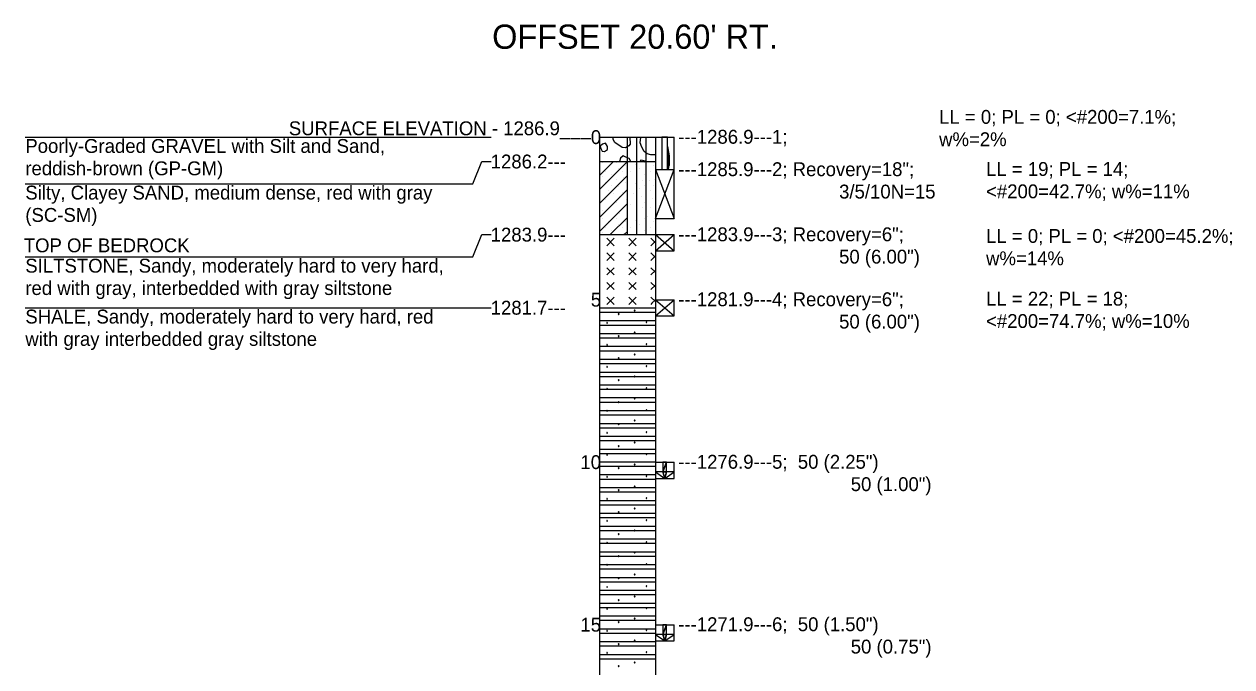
# Model space of a CAD drawing. Extents: x -6 to 173, y 24 to 64.
# Drawn here: x 138.21 to 149.01, y 44.86 to 50.61 of the extents above; entities that cross this region are included whole.
import ezdxf

# ---------------------------------------------------------------- set-up
doc = ezdxf.new("R2010")
doc.units = 0

# ---------------------------------------------------------------- blocks, each defined once
blk = doc.blocks.new('POINT_DISPLAY')
blk.add_line((0, 0), (0, 0))

msp = doc.modelspace()

# ---------------------------------------------------------------- linework, layer by layer
for points in [[(138.218, 49.598), (142.384, 49.598)], [(143.352, 49.598), (144.019, 49.598)], [(143.352, 49.598), (143.352, 39.423)], [(143.624, 49.598), (143.625, 49.534), (143.614, 49.519), (143.584, 49.503), (143.555, 49.504), (143.534, 49.519), (143.51, 49.534), (143.489, 49.549), (143.475, 49.578), (143.475, 49.598)], [(143.602, 49.38), (143.602, 49.598)], [(143.685, 49.38), (143.685, 49.598)], [(143.852, 49.441), (143.812, 49.439), (143.777, 49.449), (143.752, 49.469), (143.729, 49.508), (143.715, 49.548), (143.72, 49.598)], [(143.769, 49.38), (143.769, 49.598)], [(143.852, 49.598), (143.852, 39.423)], [(144.019, 49.307), (144.019, 49.598)], [(143.379, 49.536), (143.359, 49.518), (143.365, 49.496), (143.375, 49.471), (143.397, 49.468), (143.422, 49.488), (143.422, 49.514), (143.405, 49.544), (143.379, 49.536)], [(138.218, 49.181), (142.218, 49.181), (142.301, 49.38), (142.384, 49.38)], [(143.352, 49.38), (143.852, 49.38)], [(143.352, 49.255), (143.477, 49.38)], [(143.352, 49.13), (143.602, 49.38)], [(143.618, 49.408), (143.588, 49.42), (143.563, 49.432), (143.54, 49.41), (143.532, 49.38), (143.631, 49.38), (143.618, 49.408)], [(143.602, 48.726), (143.602, 49.38)], [(143.685, 48.726), (143.685, 49.38)], [(143.764, 49.383), (143.721, 49.391), (143.713, 49.38), (143.764, 49.38), (143.764, 49.383)], [(143.769, 48.726), (143.769, 49.38)], [(143.352, 49.005), (143.602, 49.255)], [(143.852, 49.307), (144.019, 49.307)], [(143.852, 49.307), (144.019, 48.871)], [(143.852, 48.871), (144.019, 49.307)], [(143.852, 49.307), (144.019, 49.307)], [(144.019, 48.871), (144.019, 49.307)], [(143.352, 48.88), (143.602, 49.13)], [(143.352, 48.755), (143.602, 49.005)], [(143.448, 48.726), (143.602, 48.88)], [(143.852, 48.871), (144.019, 48.871)], [(138.218, 48.527), (142.218, 48.527), (142.301, 48.726), (142.384, 48.726)], [(143.352, 48.726), (143.852, 48.726)], [(143.573, 48.726), (143.602, 48.755)], [(143.852, 48.726), (144.019, 48.58)], [(143.852, 48.58), (144.019, 48.726)], [(143.852, 48.726), (144.019, 48.726)], [(144.019, 48.58), (144.019, 48.726)], [(143.483, 48.693), (143.417, 48.627)], [(143.417, 48.693), (143.483, 48.627)], [(143.68, 48.693), (143.614, 48.627)], [(143.614, 48.693), (143.68, 48.627)], [(143.811, 48.693), (143.852, 48.652)], [(143.852, 48.668), (143.811, 48.627)], [(143.483, 48.562), (143.417, 48.496)], [(143.417, 48.562), (143.483, 48.496)], [(143.68, 48.562), (143.614, 48.496)], [(143.614, 48.562), (143.68, 48.496)], [(143.811, 48.562), (143.852, 48.521)], [(143.852, 48.537), (143.811, 48.496)], [(143.852, 48.58), (144.019, 48.58)], [(143.483, 48.43), (143.417, 48.365)], [(143.417, 48.43), (143.483, 48.365)], [(143.68, 48.43), (143.614, 48.365)], [(143.614, 48.43), (143.68, 48.365)], [(143.811, 48.43), (143.852, 48.39)], [(143.852, 48.405), (143.811, 48.365)], [(143.483, 48.299), (143.417, 48.234)], [(143.417, 48.299), (143.483, 48.234)], [(143.68, 48.299), (143.614, 48.234)], [(143.614, 48.299), (143.68, 48.234)], [(143.811, 48.299), (143.852, 48.258)], [(143.852, 48.274), (143.811, 48.234)], [(143.483, 48.168), (143.417, 48.102)], [(143.417, 48.168), (143.483, 48.102)], [(143.68, 48.168), (143.614, 48.102)], [(143.614, 48.168), (143.68, 48.102)], [(143.811, 48.168), (143.852, 48.127)], [(138.218, 48.072), (142.384, 48.072)], [(143.352, 48.072), (143.852, 48.072)], [(143.352, 48.072), (143.852, 48.072)], [(143.852, 48.143), (143.821, 48.112), (143.811, 48.102)], [(143.852, 48.144), (144.019, 47.999)], [(143.852, 47.999), (144.019, 48.144)], [(143.852, 48.144), (144.019, 48.144)], [(144.019, 47.999), (144.019, 48.144)], [(143.352, 48.032), (143.852, 48.032)], [(143.352, 47.957), (143.852, 47.957)], [(143.527, 48.016), (143.525, 48.019), (143.522, 48.019), (143.52, 48.016), (143.522, 48.013), (143.525, 48.013), (143.527, 48.016)], [(143.67, 48.048), (143.668, 48.05), (143.665, 48.05), (143.663, 48.048), (143.665, 48.045), (143.668, 48.045), (143.67, 48.048)], [(143.775, 47.943), (143.773, 47.946), (143.77, 47.946), (143.768, 47.943), (143.77, 47.94), (143.773, 47.94), (143.775, 47.943)], [(143.852, 47.999), (144.019, 47.999)], [(143.352, 47.917), (143.852, 47.917)], [(143.352, 47.842), (143.852, 47.842)], [(143.422, 47.937), (143.421, 47.94), (143.417, 47.94), (143.416, 47.937), (143.417, 47.934), (143.421, 47.934), (143.422, 47.937)], [(143.67, 47.851), (143.668, 47.854), (143.665, 47.854), (143.663, 47.851), (143.665, 47.848), (143.668, 47.848), (143.67, 47.851)], [(143.352, 47.803), (143.852, 47.803)], [(143.352, 47.727), (143.852, 47.727)], [(143.422, 47.74), (143.421, 47.743), (143.417, 47.743), (143.416, 47.74), (143.417, 47.737), (143.421, 47.737), (143.422, 47.74)], [(143.527, 47.819), (143.525, 47.822), (143.522, 47.822), (143.52, 47.819), (143.522, 47.816), (143.525, 47.816), (143.527, 47.819)], [(143.775, 47.746), (143.773, 47.749), (143.77, 47.749), (143.768, 47.746), (143.77, 47.744), (143.773, 47.744), (143.775, 47.746)], [(143.352, 47.688), (143.852, 47.688)], [(143.527, 47.622), (143.525, 47.625), (143.522, 47.625), (143.52, 47.622), (143.522, 47.619), (143.525, 47.619), (143.527, 47.622)], [(143.67, 47.654), (143.668, 47.657), (143.665, 47.657), (143.663, 47.654), (143.665, 47.651), (143.668, 47.651), (143.67, 47.654)], [(143.352, 47.612), (143.852, 47.612)], [(143.352, 47.573), (143.852, 47.573)], [(143.422, 47.543), (143.421, 47.546), (143.417, 47.546), (143.416, 47.543), (143.417, 47.54), (143.421, 47.54), (143.422, 47.543)], [(143.775, 47.55), (143.773, 47.552), (143.77, 47.552), (143.768, 47.55), (143.77, 47.547), (143.773, 47.547), (143.775, 47.55)], [(143.352, 47.497), (143.852, 47.497)], [(143.352, 47.458), (143.852, 47.458)], [(143.527, 47.425), (143.525, 47.428), (143.522, 47.428), (143.52, 47.425), (143.522, 47.422), (143.525, 47.422), (143.527, 47.425)], [(143.67, 47.457), (143.668, 47.46), (143.665, 47.46), (143.663, 47.457), (143.665, 47.454), (143.668, 47.454), (143.67, 47.457)], [(143.352, 47.383), (143.852, 47.383)], [(143.352, 47.343), (143.852, 47.343)], [(143.422, 47.346), (143.421, 47.349), (143.417, 47.349), (143.416, 47.346), (143.417, 47.343), (143.421, 47.343), (143.422, 47.346)], [(143.775, 47.353), (143.773, 47.356), (143.77, 47.356), (143.768, 47.353), (143.77, 47.35), (143.773, 47.35), (143.775, 47.353)], [(143.352, 47.268), (143.852, 47.268)], [(143.352, 47.228), (143.852, 47.228)], [(143.527, 47.228), (143.525, 47.231), (143.522, 47.231), (143.52, 47.228), (143.522, 47.225), (143.525, 47.225), (143.527, 47.228)], [(143.67, 47.26), (143.668, 47.263), (143.665, 47.263), (143.663, 47.26), (143.665, 47.257), (143.668, 47.257), (143.67, 47.26)], [(143.352, 47.153), (143.852, 47.153)], [(143.352, 47.114), (143.852, 47.114)], [(143.422, 47.149), (143.421, 47.152), (143.417, 47.152), (143.416, 47.149), (143.417, 47.146), (143.421, 47.146), (143.422, 47.149)], [(143.775, 47.156), (143.773, 47.159), (143.77, 47.159), (143.768, 47.156), (143.77, 47.153), (143.773, 47.153), (143.775, 47.156)], [(143.352, 47.038), (143.852, 47.038)], [(143.352, 46.999), (143.852, 46.999)], [(143.527, 47.031), (143.525, 47.034), (143.522, 47.034), (143.52, 47.032), (143.522, 47.029), (143.525, 47.029), (143.527, 47.031)], [(143.67, 47.063), (143.668, 47.066), (143.665, 47.066), (143.663, 47.063), (143.665, 47.061), (143.668, 47.061), (143.67, 47.063)], [(143.352, 46.923), (143.852, 46.923)], [(143.352, 46.884), (143.852, 46.884)], [(143.422, 46.953), (143.421, 46.955), (143.417, 46.955), (143.416, 46.953), (143.417, 46.95), (143.421, 46.95), (143.422, 46.953)], [(143.67, 46.867), (143.668, 46.869), (143.665, 46.869), (143.663, 46.867), (143.665, 46.864), (143.668, 46.864), (143.67, 46.867)], [(143.775, 46.959), (143.773, 46.962), (143.77, 46.962), (143.768, 46.959), (143.77, 46.956), (143.773, 46.956), (143.775, 46.959)], [(143.352, 46.808), (143.852, 46.808)], [(143.352, 46.769), (143.852, 46.769)], [(143.422, 46.756), (143.421, 46.759), (143.417, 46.759), (143.416, 46.756), (143.417, 46.753), (143.421, 46.753), (143.422, 46.756)], [(143.527, 46.835), (143.525, 46.838), (143.522, 46.838), (143.52, 46.835), (143.522, 46.832), (143.525, 46.832), (143.527, 46.835)], [(143.775, 46.762), (143.773, 46.765), (143.77, 46.765), (143.768, 46.762), (143.77, 46.759), (143.773, 46.759), (143.775, 46.762)], [(143.352, 46.694), (143.852, 46.694)], [(143.352, 46.654), (143.852, 46.654)], [(143.67, 46.67), (143.668, 46.672), (143.665, 46.672), (143.663, 46.67), (143.665, 46.667), (143.668, 46.667), (143.67, 46.67)], [(143.852, 46.691), (144.019, 46.691)], [(144.019, 46.545), (144.019, 46.691)], [(143.352, 46.579), (143.852, 46.579)], [(143.352, 46.539), (143.852, 46.539)], [(143.422, 46.559), (143.421, 46.562), (143.417, 46.562), (143.416, 46.559), (143.417, 46.556), (143.421, 46.556), (143.422, 46.559)], [(143.527, 46.638), (143.525, 46.641), (143.522, 46.641), (143.52, 46.638), (143.522, 46.635), (143.525, 46.635), (143.527, 46.638)], [(143.775, 46.565), (143.773, 46.568), (143.77, 46.568), (143.768, 46.565), (143.77, 46.563), (143.773, 46.563), (143.775, 46.565)], [(143.852, 46.545), (144.019, 46.545)], [(143.352, 46.464), (143.852, 46.464)], [(143.527, 46.441), (143.525, 46.444), (143.522, 46.444), (143.52, 46.441), (143.522, 46.438), (143.525, 46.438), (143.527, 46.441)], [(143.67, 46.473), (143.668, 46.476), (143.665, 46.476), (143.663, 46.473), (143.665, 46.47), (143.668, 46.47), (143.67, 46.473)], [(143.352, 46.425), (143.852, 46.425)], [(143.352, 46.349), (143.852, 46.349)], [(143.422, 46.362), (143.421, 46.365), (143.417, 46.365), (143.416, 46.362), (143.417, 46.359), (143.421, 46.359), (143.422, 46.362)], [(143.775, 46.368), (143.773, 46.371), (143.77, 46.371), (143.768, 46.368), (143.77, 46.366), (143.773, 46.366), (143.775, 46.368)], [(143.352, 46.31), (143.852, 46.31)], [(143.352, 46.234), (143.852, 46.234)], [(143.527, 46.244), (143.525, 46.247), (143.522, 46.247), (143.52, 46.244), (143.522, 46.241), (143.525, 46.241), (143.527, 46.244)], [(143.67, 46.276), (143.668, 46.279), (143.665, 46.279), (143.663, 46.276), (143.665, 46.273), (143.668, 46.273), (143.67, 46.276)], [(143.352, 46.195), (143.852, 46.195)], [(143.352, 46.119), (143.852, 46.119)], [(143.422, 46.165), (143.421, 46.168), (143.417, 46.168), (143.416, 46.165), (143.417, 46.162), (143.421, 46.162), (143.422, 46.165)], [(143.775, 46.172), (143.773, 46.175), (143.77, 46.175), (143.768, 46.172), (143.77, 46.169), (143.773, 46.169), (143.775, 46.172)], [(143.352, 46.08), (143.852, 46.08)], [(143.352, 46.005), (143.852, 46.005)], [(143.527, 46.047), (143.525, 46.05), (143.522, 46.05), (143.52, 46.047), (143.522, 46.044), (143.525, 46.044), (143.527, 46.047)], [(143.67, 46.079), (143.668, 46.082), (143.665, 46.082), (143.663, 46.079), (143.665, 46.076), (143.668, 46.076), (143.67, 46.079)], [(143.352, 45.965), (143.852, 45.965)], [(143.422, 45.968), (143.421, 45.971), (143.417, 45.971), (143.416, 45.968), (143.417, 45.965), (143.421, 45.965), (143.422, 45.968)], [(143.775, 45.975), (143.773, 45.978), (143.77, 45.978), (143.768, 45.975), (143.77, 45.972), (143.773, 45.972), (143.775, 45.975)], [(143.352, 45.89), (143.852, 45.89)], [(143.352, 45.85), (143.852, 45.85)], [(143.527, 45.85), (143.525, 45.853), (143.522, 45.853), (143.52, 45.85), (143.522, 45.848), (143.525, 45.848), (143.527, 45.85)], [(143.67, 45.882), (143.668, 45.885), (143.665, 45.885), (143.663, 45.882), (143.665, 45.879), (143.668, 45.879), (143.67, 45.882)], [(143.352, 45.775), (143.852, 45.775)], [(143.352, 45.736), (143.852, 45.736)], [(143.422, 45.771), (143.421, 45.774), (143.417, 45.774), (143.416, 45.771), (143.417, 45.769), (143.421, 45.769), (143.422, 45.771)], [(143.67, 45.685), (143.668, 45.688), (143.665, 45.688), (143.663, 45.685), (143.665, 45.683), (143.668, 45.683), (143.67, 45.685)], [(143.775, 45.778), (143.773, 45.781), (143.77, 45.781), (143.768, 45.778), (143.77, 45.775), (143.773, 45.775), (143.775, 45.778)], [(143.352, 45.66), (143.852, 45.66)], [(143.352, 45.621), (143.852, 45.621)], [(143.422, 45.575), (143.421, 45.577), (143.417, 45.577), (143.416, 45.575), (143.417, 45.572), (143.421, 45.572), (143.422, 45.575)], [(143.527, 45.654), (143.525, 45.656), (143.522, 45.656), (143.52, 45.654), (143.522, 45.651), (143.525, 45.651), (143.527, 45.654)], [(143.775, 45.581), (143.773, 45.584), (143.77, 45.584), (143.768, 45.581), (143.77, 45.578), (143.773, 45.578), (143.775, 45.581)], [(143.352, 45.545), (143.852, 45.545)], [(143.352, 45.506), (143.852, 45.506)], [(143.527, 45.457), (143.525, 45.46), (143.522, 45.46), (143.52, 45.457), (143.522, 45.454), (143.525, 45.454), (143.527, 45.457)], [(143.67, 45.489), (143.668, 45.491), (143.665, 45.491), (143.663, 45.489), (143.665, 45.486), (143.668, 45.486), (143.67, 45.489)], [(143.352, 45.43), (143.852, 45.43)], [(143.352, 45.391), (143.852, 45.391)], [(143.422, 45.378), (143.421, 45.381), (143.417, 45.381), (143.416, 45.378), (143.417, 45.375), (143.421, 45.375), (143.422, 45.378)], [(143.775, 45.384), (143.773, 45.387), (143.77, 45.387), (143.768, 45.384), (143.77, 45.381), (143.773, 45.381), (143.775, 45.384)], [(143.352, 45.316), (143.852, 45.316)], [(143.352, 45.276), (143.852, 45.276)], [(143.527, 45.26), (143.525, 45.263), (143.522, 45.263), (143.52, 45.26), (143.522, 45.257), (143.525, 45.257), (143.527, 45.26)], [(143.67, 45.292), (143.668, 45.295), (143.665, 45.295), (143.663, 45.292), (143.665, 45.289), (143.668, 45.289), (143.67, 45.292)], [(143.352, 45.201), (143.852, 45.201)], [(143.352, 45.161), (143.852, 45.161)], [(143.422, 45.181), (143.421, 45.184), (143.417, 45.184), (143.416, 45.181), (143.417, 45.178), (143.421, 45.178), (143.422, 45.181)], [(143.775, 45.187), (143.773, 45.19), (143.77, 45.19), (143.768, 45.187), (143.77, 45.185), (143.773, 45.185), (143.775, 45.187)], [(143.852, 45.237), (144.019, 45.237)], [(144.019, 45.092), (144.019, 45.237)], [(143.352, 45.086), (143.852, 45.086)], [(143.352, 45.047), (143.852, 45.047)], [(143.527, 45.063), (143.525, 45.066), (143.522, 45.066), (143.52, 45.063), (143.522, 45.06), (143.525, 45.06), (143.527, 45.063)], [(143.67, 45.095), (143.668, 45.098), (143.665, 45.098), (143.663, 45.095), (143.665, 45.092), (143.668, 45.092), (143.67, 45.095)], [(143.852, 45.092), (144.019, 45.092)], [(143.352, 44.971), (143.852, 44.971)], [(143.352, 44.932), (143.852, 44.932)], [(143.422, 44.984), (143.421, 44.987), (143.417, 44.987), (143.416, 44.984), (143.417, 44.981), (143.421, 44.981), (143.422, 44.984)], [(143.775, 44.991), (143.773, 44.993), (143.77, 44.993), (143.768, 44.991), (143.77, 44.988), (143.773, 44.988), (143.775, 44.991)], [(143.527, 44.866), (143.525, 44.869), (143.522, 44.869), (143.52, 44.866), (143.522, 44.863), (143.525, 44.863), (143.527, 44.866)], [(143.67, 44.898), (143.668, 44.901), (143.665, 44.901), (143.663, 44.898), (143.665, 44.895), (143.668, 44.895), (143.67, 44.898)]]:
    msp.add_lwpolyline(points)
for points in [[(143.91, 49.598), (143.91, 49.307), (143.96, 49.307), (143.96, 49.598)], [(143.975, 49.431), (143.969, 49.473), (143.96, 49.513), (143.975, 49.431)], [(143.96, 49.513), (143.96, 49.307), (143.975, 49.431), (143.96, 49.513)], [(143.96, 49.307), (143.975, 49.348), (143.975, 49.431), (143.96, 49.307)], [(143.96, 49.307), (143.969, 49.307), (143.975, 49.348), (143.96, 49.307)], [(143.975, 49.348), (143.977, 49.389), (143.975, 49.431), (143.975, 49.348)], [(143.919, 46.604), (143.952, 46.604), (143.952, 46.691), (143.919, 46.604)], [(143.919, 46.604), (143.952, 46.691), (143.919, 46.691), (143.919, 46.604)], [(143.919, 46.604), (143.852, 46.604), (143.935, 46.545), (143.919, 46.604)], [(143.919, 46.604), (143.935, 46.545), (143.952, 46.604), (143.919, 46.604)], [(143.935, 46.545), (144.019, 46.604), (143.952, 46.604), (143.935, 46.545)], [(143.919, 45.15), (143.852, 45.15), (143.935, 45.092), (143.919, 45.15)], [(143.919, 45.15), (143.952, 45.15), (143.952, 45.237), (143.919, 45.15)], [(143.919, 45.15), (143.952, 45.237), (143.919, 45.237), (143.919, 45.15)], [(143.919, 45.15), (143.935, 45.092), (143.952, 45.15), (143.919, 45.15)], [(143.935, 45.092), (144.019, 45.15), (143.952, 45.15), (143.935, 45.092)]]:
    msp.add_lwpolyline(points, close=True)

# ---------------------------------------------------------------- block references
at = {"xscale": 0.01, "yscale": 0.01}
for p in [(143.381, 49.367), (143.506, 49.367), (143.671, 49.355), (143.756, 49.367), (143.356, 49.317), (143.381, 49.242), (143.406, 49.292), (143.431, 49.342), (143.456, 49.267), (143.523, 49.319), (143.556, 49.292), (143.581, 49.342), (143.631, 49.292), (143.681, 49.242), (143.706, 49.317), (143.756, 49.267), (143.806, 49.292), (143.831, 49.342), (143.356, 49.142), (143.406, 49.192), (143.456, 49.167), (143.506, 49.217), (143.52, 49.159), (143.569, 49.235), (143.581, 49.192), (143.67, 49.179), (143.706, 49.142), (143.738, 49.214), (143.756, 49.167), (143.798, 49.21), (143.831, 49.167), (143.847, 49.217), (143.406, 49.042), (143.431, 49.117), (143.481, 49.092), (143.531, 49.067), (143.559, 49.107), (143.59, 49.042), (143.606, 49.117), (143.656, 49.092), (143.681, 49.042), (143.731, 49.067), (143.806, 49.117), (143.824, 49.048), (143.356, 48.992), (143.381, 48.942), (143.431, 48.967), (143.506, 49.017), (143.531, 48.917), (143.556, 48.967), (143.631, 48.992), (143.681, 48.942), (143.732, 48.967), (143.756, 49.017), (143.806, 48.967), (143.851, 48.917), (143.356, 48.817), (143.381, 48.867), (143.431, 48.842), (143.506, 48.867), (143.523, 48.819), (143.581, 48.842), (143.606, 48.892), (143.671, 48.855), (143.706, 48.817), (143.756, 48.867), (143.781, 48.892), (143.831, 48.842), (143.381, 48.742), (143.406, 48.792), (143.456, 48.767), (143.556, 48.792), (143.569, 48.735), (143.631, 48.792), (143.681, 48.742), (143.756, 48.767), (143.806, 48.792)]:
    msp.add_blockref('POINT_DISPLAY', p, dxfattribs=at)

# ---------------------------------------------------------------- texts
for s, height, p in [("OFFSET 20.60' RT.", 0.217, (142.392, 50.388)), ('LL = 0; PL = 0; <#200=7.1%;', 0.124, (146.388, 49.717)), ('SURFACE ELEVATION - 1286.9___', 0.124, (140.574, 49.615)), ('Poorly-Graded GRAVEL with Silt and Sand,', 0.124, (138.218, 49.457)), ('0', 0.124, (143.274, 49.536)), ('---1286.9---1;', 0.124, (144.056, 49.539)), ('w%=2%', 0.124, (146.388, 49.517)), ('reddish-brown (GP-GM)', 0.124, (138.218, 49.257)), ('1286.2---', 0.124, (142.379, 49.318)), ('---1285.9---2; Recovery=18";', 0.124, (144.056, 49.249)), ('LL = 19; PL = 14;', 0.124, (146.808, 49.251)), ('Silty, Clayey SAND, medium dense, red with gray', 0.124, (138.218, 49.04)), ('3/5/10N=15', 0.124, (145.494, 49.049)), ('<#200=42.7%; w%=11%', 0.124, (146.808, 49.051)), ('(SC-SM)', 0.124, (138.218, 48.84)), ('1283.9---', 0.124, (142.379, 48.664)), ('---1283.9---3; Recovery=6";', 0.124, (144.056, 48.667)), ('LL = 0; PL = 0; <#200=45.2%;', 0.124, (146.808, 48.652)), ('TOP OF BEDROCK', 0.124, (138.204, 48.568)), ('50 (6.00")', 0.124, (145.494, 48.467)), ('SILTSTONE, Sandy, moderately hard to very hard,', 0.124, (138.218, 48.386)), ('w%=14%', 0.124, (146.808, 48.452)), ('red with gray, interbedded with gray siltstone', 0.124, (138.218, 48.186)), ('5', 0.124, (143.274, 48.082)), ('---1281.9---4; Recovery=6";', 0.124, (144.056, 48.086)), ('LL = 22; PL = 18;', 0.124, (146.808, 48.091)), ('SHALE, Sandy, moderately hard to very hard, red', 0.124, (138.218, 47.931)), ('1281.7---', 0.124, (142.379, 48.01)), ('50 (6.00")', 0.124, (145.494, 47.886)), ('<#200=74.7%; w%=10%', 0.124, (146.808, 47.891)), ('with gray interbedded gray siltstone', 0.124, (138.218, 47.731)), ('---1276.9---5;  50 (2.25")', 0.124, (144.056, 46.632)), ('10', 0.124, (143.181, 46.629)), ('50 (1.00")', 0.124, (145.598, 46.432)), ('15', 0.124, (143.181, 45.175)), ('---1271.9---6;  50 (1.50")', 0.124, (144.056, 45.179)), ('50 (0.75")', 0.124, (145.598, 44.979))]:
    msp.add_text(s, height=height).set_placement(p)

doc.saveas('drawing.dxf')
